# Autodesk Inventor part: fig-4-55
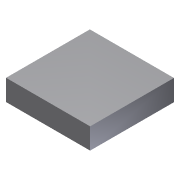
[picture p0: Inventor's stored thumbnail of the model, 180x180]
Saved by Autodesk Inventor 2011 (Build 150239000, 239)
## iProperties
Created: 2010-02
Part Number: fig-4-55
Document SubType Name: Modeling
Designer: CADSoft
Density: 1 g/cm^3
Author: CADSoft
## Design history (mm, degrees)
sketch "Sketch1"
  geometry: L1 (-20.026, 19.961)-(0, 19.961); L2 (0, 19.961)-(0, 0); L3 (0, 0)-(-20.026, 0); L4 (-20.026, 0)-(-20.026, 19.961)
  constraints: 8 end point
extrude "Extrusion1" new body sketch "Sketch1" distance "d0" = 5; taper "d1" = 0 deg
body "Solid1"
